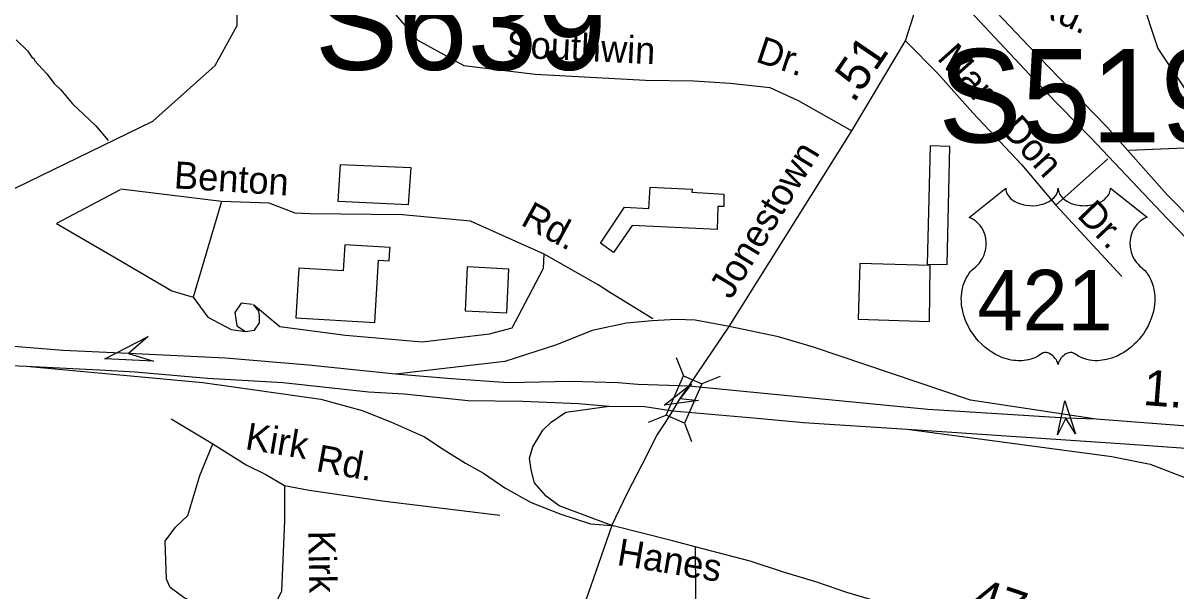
# Model space of a CAD drawing. Extents: x 1547597 to 1699558, y 810033 to 920809.
# Drawn here: x 1602112 to 1606161, y 847300 to 849294 of the extents above; entities that cross this region are included whole.
import ezdxf

# ---------------------------------------------------------------- set-up
doc = ezdxf.new("R2010")
doc.units = 0
for name, color, linetype in [('Exist Cultural Warehouse Building Footprint', 7, 'Continuous'), ('Exist Hydrographic Creek Single Shore', 7, 'Continuous'), ('Exist Hydrographic Misc Water Feature', 7, 'Continuous'), ('Exist Road Non-System Type 51', 7, 'Continuous'), ('Exist Road Non-System Type 51 Label', 7, 'Continuous'), ('Exist Road Primary Interstate Structure Ovrhead Sign Attributed CELL', 7, 'Continuous'), ('Exist Road Primary Interstate Structure Ovrhead Sign Number Label', 7, 'Continuous'), ('Exist Road Primary US Divided Attributed', 7, 'Continuous'), ('Exist Road Primary US Mileage Hundredths English Label', 7, 'Continuous'), ('Exist Road Primary US Ramp 1 Lane  Attributed', 7, 'Continuous'), ('Exist Road Primary US Shield CELL', 7, 'Continuous'), ('Exist Road Primary US Shield Number Label', 7, 'Continuous'), ('Exist Road Secondary Mileage Hundredths English Label', 7, 'Continuous'), ('Exist Road Secondary Structure Standard Bridge Attributed CELL', 7, 'Continuous'), ('Exist Road Secondary Structure Standard Bridge CELL', 7, 'Continuous'), ('Exist Road Secondary Type 51 Attributed', 7, 'Continuous'), ('Exist Road Secondary Type 51 Label', 7, 'Continuous'), ('Exist Utilities Electrical Transmission Line', 7, 'Continuous')]:
    doc.layers.add(name, color=color, linetype=linetype)

msp = doc.modelspace()

# ---------------------------------------------------------------- linework, layer by layer
at = {"layer": 'Exist Cultural Warehouse Building Footprint'}
for points in [[(1605286.8, 848447.3), (1605356.8, 848445.9), (1605366.7, 848861), (1605298, 848862.4)], [(1603227, 848797.3), (1603474, 848786.9), (1603463.9, 848655.4), (1603218.1, 848667.4)], [(1604139.9, 848520.7), (1604223.7, 848647.5), (1604309.6, 848642.4), (1604314.7, 848718.3), (1604461.3, 848710.7), (1604460.9, 848699.7), (1604572.5, 848693), (1604572.5, 848650), (1604552.2, 848650), (1604549.7, 848569), (1604250.5, 848583.1), (1604185.8, 848488.1)], [(1603069.7, 848258.4), (1603347.2, 848242), (1603360.2, 848461.2), (1603398, 848458.9), (1603400.2, 848497.3), (1603400.8, 848506), (1603241.4, 848515.5), (1603236, 848423.8), (1603080.1, 848433)], [(1603671, 848437.5), (1603665, 848283.8), (1603810.6, 848275.9), (1603818.2, 848430.2)], [(1605050.4, 848449.2), (1605044.8, 848254.3), (1605295.6, 848245.9), (1605297, 848442.2)]]:
    msp.add_lwpolyline(points, close=True, dxfattribs=at)
at = {"layer": 'Exist Hydrographic Creek Single Shore'}
msp.add_lwpolyline([(1601996.7, 848672.3), (1602567.6, 848949.6), (1602786.6, 849145.4), (1602863.6, 849285), (1602859.6, 849610.1), (1602806.6, 849988.7), (1602824.7, 850162.3), (1602904.6, 850485.7), (1602936.7, 850702.7), (1602989.1, 850819.4), (1603267.6, 850997.3), (1603446.2, 851092.6), (1603489, 851168.8), (1603543.8, 851395.2), (1603678.6, 851694.4), (1603816.6, 851990.4), (1603873.5, 852138.8)], dxfattribs=at)
at = {"layer": 'Exist Hydrographic Misc Water Feature'}
msp.add_lwpolyline([(1602087.1, 849235.5), (1602128.5, 849194.9), (1602142.3, 849174.7), (1602150.2, 849168.6), (1602152.1, 849162.6), (1602195.5, 849116), (1602220.9, 849081.6), (1602244.6, 849059.3), (1602285.9, 849010.7), (1602366.8, 848933.6), (1602411.2, 848882.2)], dxfattribs=at)
at = {"layer": 'Exist Road Non-System Type 51'}
for points in [[(1603341.7, 849798.4), (1603321, 849576.4), (1603341.5, 849455.7), (1603413.3, 849332.6), (1603495.3, 849235.1), (1603659.4, 849145.2), (1603910.7, 849114.4), (1604297.9, 849093.9), (1604467.1, 849091.3), (1604595.3, 849083.6), (1604733.8, 849068.3), (1604833.8, 849022.1), (1605022.8, 848915.5)], [(1606035.8, 849389.8), (1606097.5, 849204.3), (1606189.1, 849066.9), (1606280.6, 848927.2), (1606321.8, 848883.7)], [(1605210.5, 849232.1), (1605324.1, 849117.5), (1605447.6, 848979.1), (1605617.7, 848797.4), (1605738.3, 848654.7)], [(1606321.8, 848883.7), (1606276, 848858.5), (1605994.6, 848847)], [(1605921.3, 848817.3), (1605738.3, 848654.7)], [(1602452.4, 848708.3), (1602229.3, 848590.2)], [(1602808.8, 848667.2), (1602454.9, 848710.9)], [(1602808.8, 848667.2), (1602708.8, 848331.1)], [(1603942.2, 848482.5), (1603683.2, 848597.9), (1603444.7, 848621), (1603119.1, 848623.6), (1603067.8, 848626.2), (1602975.5, 848662.1), (1602808.8, 848667.2)], [(1605738.3, 848654.7), (1605970.6, 848403.6)], [(1602229.3, 848590.2), (1602444.7, 848464.5), (1602634.4, 848354.2), (1602708.8, 848331.1)], [(1602921.6, 848305.4), (1603013.9, 848228.4), (1603244.7, 848197.6), (1603513.9, 848174.5), (1603749.8, 848202.8), (1603829.3, 848223.3), (1603875.5, 848310.5), (1603939.6, 848433.7), (1603942.2, 848482.5)], [(1604323.6, 848255.1), (1604174.8, 848346.7), (1604131.2, 848374.9), (1603942.2, 848482.5)], [(1602708.8, 848331.1), (1602760.1, 848261.8), (1602842.1, 848218.1), (1602893.4, 848210.5)], [(1602916.5, 848305.4), (1602878, 848310.5), (1602855, 848277.2), (1602862.6, 848231), (1602893.4, 848210.5), (1602924.2, 848215.6), (1602942.1, 848241.2), (1602942.1, 848266.9), (1602939.6, 848282.3), (1602921.6, 848305.4)], [(1602632.2, 847903.9), (1602778.3, 847816.2)], [(1602962.8, 847180.7), (1602833.1, 847202.6), (1602677.9, 847275.7), (1602628.6, 847312.3), (1602615.8, 847341.5), (1602610.3, 847474.9), (1602646.9, 847524.3), (1602690.7, 847564.5), (1602732.7, 847705.2), (1602778.3, 847816.2)], [(1602778.3, 847816.2), (1602895.2, 847743.1), (1602964.6, 847708.3), (1603030.3, 847670.5)], [(1603030.3, 847670.5), (1603030.3, 847546.2), (1603019.4, 847299.5), (1602979.2, 847215.4), (1602962.8, 847180.7)], [(1603030.3, 847670.5), (1603116.1, 847653.5), (1603382.8, 847615.1), (1603786.4, 847565.8)], [(1604179.3, 847529.3), (1604040.1, 847129.7), (1603925.9, 846807)], [(1604471.8, 847454.2), (1604477.1, 846806.5)]]:
    msp.add_lwpolyline(points, dxfattribs=at)
at = {"layer": 'Exist Road Primary Interstate Structure Ovrhead Sign Attributed CELL'}
for points in [[(1602569.3, 848106.7), (1602398.8, 848115.3), (1602550.7, 848193.1), (1602482.2, 848133.2)], [(1605744.9, 847848.5), (1605770.6, 847967.7), (1605808, 847851.6), (1605773.6, 847906.8)]]:
    msp.add_lwpolyline(points, close=True, dxfattribs=at)
at = {"layer": 'Exist Road Primary US Divided Attributed'}
for points in [[(1603419.9, 848061.2), (1603114.3, 848092.3), (1602822.5, 848117.4), (1602482.2, 848133.2), (1602251.6, 848144), (1602064.6, 848159.3), (1601728.5, 848169.4), (1601520.5, 848164.7), (1601065.6, 848149.1), (1600583.5, 848138.5), (1600345.2, 848131.5), (1599996.2, 848126.1), (1599882.8, 848124.5)], [(1599705.6, 848058.6), (1599908.3, 848059.2), (1600130.5, 848064.5), (1600361.8, 848073.3), (1600468.6, 848076), (1600705.6, 848082.6), (1600979.1, 848087.3), (1601274, 848094.3), (1601502.3, 848105), (1601786.7, 848104.7), (1602122.6, 848089.2)], [(1602122.6, 848089.2), (1602379.8, 848076), (1602505.4, 848069.5), (1602759.8, 848047.1), (1603025, 848032), (1603324.9, 847999.1), (1603450.2, 847992.6), (1603675.4, 847968.5), (1603865.5, 847965.8), (1604062, 847958.2), (1604170.7, 847948.4)], [(1604449.6, 848019.4), (1604271.1, 848024.5), (1604201.6, 848030.1), (1604035.6, 848035.1), (1603815.2, 848030.2), (1603616, 848044.4), (1603419.9, 848061.2)], [(1605880.9, 847903.3), (1605773.6, 847906.8), (1605289.3, 847936.9), (1604449.6, 848019.4)], [(1604170.7, 847948.4), (1604294.9, 847947.7), (1604393.5, 847932.6)], [(1604393.5, 847932.6), (1604689.4, 847907.1), (1604852.6, 847891.8), (1605217.1, 847868.3)], [(1605217.1, 847868.3), (1606000.2, 847815.6), (1606342, 847790.1), (1606658.4, 847762.4), (1606838.5, 847750.4), (1607017.4, 847737.7), (1607165.1, 847724), (1607331.3, 847713.2), (1607466.4, 847708.9), (1607585.8, 847712.7), (1607706.7, 847722.7)], [(1606537.3, 847865.3), (1606352.3, 847866.3), (1605880.9, 847903.3)]]:
    msp.add_lwpolyline(points, dxfattribs=at)
at = {"layer": 'Exist Road Primary US Ramp 1 Lane  Attributed'}
for points in [[(1604591.4, 848228.5), (1604472.7, 848251.2), (1604404.9, 848252.6), (1604320.7, 848248.1), (1604230.7, 848239.7), (1604110.3, 848213.9), (1603984.8, 848163.9), (1603804, 848105.3), (1603419.9, 848061.2)], [(1605880.9, 847903.3), (1605439.1, 847969.9), (1604888.2, 848156), (1604764.6, 848191.7), (1604591.4, 848228.5)], [(1602122.6, 848089.2), (1602742.7, 848031.5), (1603158.1, 847973.8), (1603302.4, 847933.4), (1603406.2, 847893), (1603521.6, 847841), (1603590.8, 847794.8), (1603665.8, 847748.7), (1603729.3, 847714), (1603804.3, 847662.1), (1603896.6, 847610.1), (1604000.5, 847569.7), (1604104.3, 847535.1), (1604179.3, 847529.3)], [(1604179.3, 847529.3), (1603994.7, 847598.6), (1603948.6, 847633.2), (1603908.2, 847679.4), (1603896.6, 847725.6), (1603890.9, 847766), (1603902.4, 847806.4), (1603919.7, 847835.3), (1603937, 847864.1), (1603965.9, 847893), (1604017.8, 847927.6), (1604170.7, 847948.4)], [(1605217.1, 847868.3), (1605935.1, 847772.4), (1606069.9, 847744.7), (1606258.6, 847672.4), (1606386.7, 847609.8), (1606623.3, 847465.6), (1606799.3, 847336.5), (1606924.5, 847240.2)]]:
    msp.add_lwpolyline(points, dxfattribs=at)
at = {"layer": 'Exist Road Primary US Shield CELL'}
msp.add_lwpolyline([(1605562.7, 848714.2), (1605563.1, 848708.8), (1605564.4, 848702.5), (1605565.3, 848699.3), (1605568.3, 848693), (1605573.2, 848685.7), (1605580, 848678.4), (1605587.6, 848672.1), (1605592.8, 848668.8), (1605601.6, 848664.1), (1605611.5, 848659.9), (1605622.6, 848656.7), (1605633.9, 848654.4), (1605646.3, 848653.1), (1605658.5, 848652.8), (1605671.8, 848653.8), (1605686.3, 848656.6), (1605693.1, 848658.4), (1605700.6, 848661), (1605707.6, 848663.9), (1605715.3, 848668), (1605721.4, 848671.9), (1605726.2, 848675.4), (1605733.1, 848681.9), (1605738.5, 848688.7), (1605740.8, 848692.5), (1605742.8, 848696.1), (1605745.5, 848703.9), (1605746.2, 848707.3), (1605746.8, 848714.4), (1605747.2, 848708.5), (1605747.8, 848704.7), (1605748.8, 848701.1), (1605750.3, 848697.2), (1605753.1, 848691.7), (1605756.1, 848687.2), (1605761.8, 848680.4), (1605765.4, 848677.1), (1605768.7, 848674.4), (1605777.4, 848668.4), (1605787.6, 848663.2), (1605792.6, 848661), (1605797.8, 848659.2), (1605804.3, 848657.2), (1605811.1, 848655.6), (1605817.8, 848654.5), (1605824.6, 848653.5), (1605831.6, 848653), (1605837.3, 848652.8), (1605844.3, 848652.9), (1605850.7, 848653.3), (1605857.3, 848654.1), (1605864.6, 848655.3), (1605870.5, 848656.6), (1605878.2, 848658.6), (1605885.2, 848661.1), (1605891.4, 848663.8), (1605899.3, 848668), (1605905.8, 848672), (1605910.5, 848675.8), (1605916.1, 848681), (1605921.4, 848687.1), (1605924.5, 848691.6), (1605926.8, 848696.2), (1605928.8, 848701.1), (1605930.1, 848706.3), (1605930.7, 848710.7), (1605930.8, 848714.6), (1606059.4, 848612.1), (1606056.4, 848611), (1606049.4, 848607.5), (1606043.8, 848604.3), (1606035, 848598), (1606031.2, 848594.6), (1606027.4, 848591.1), (1606023.9, 848587.3), (1606020.8, 848583.7), (1606017.1, 848578.5), (1606013.7, 848573.4), (1606010.5, 848567.7), (1606008.1, 848562.7), (1606004.1, 848552.4), (1606002.2, 848545.8), (1606001, 848540.3), (1605999.5, 848528.8), (1605999.1, 848523.4), (1605999.1, 848518), (1605999.4, 848512.3), (1606000, 848506.8), (1606000.9, 848501.1), (1606001.9, 848496.1), (1606003.5, 848489.9), (1606005.7, 848482.8), (1606008.5, 848475.9), (1606014.4, 848464.7), (1606022, 848453.3), (1606027.4, 848446.9), (1606032.7, 848441.4), (1606040.6, 848434.8), (1606044.9, 848431), (1606049.9, 848426), (1606057.9, 848416.7), (1606061.2, 848412.3), (1606064.5, 848407.3), (1606067.5, 848402.2), (1606070.6, 848396.8), (1606073, 848392), (1606077.5, 848381), (1606080.8, 848370.2), (1606082.3, 848364.6), (1606084.7, 848352), (1606085.6, 848345.8), (1606086.6, 848333.5), (1606086.7, 848318.6), (1606085.5, 848304.4), (1606082.9, 848287.9), (1606080.7, 848278.1), (1606077.3, 848266.6), (1606074, 848256.6), (1606068.1, 848242), (1606062.9, 848231.3), (1606056.2, 848218.9), (1606051.5, 848211.4), (1606046.1, 848203.3), (1606039.4, 848194), (1606031.5, 848184.1), (1606022, 848173.7), (1606014.3, 848166.1), (1606004.3, 848157.1), (1605998.2, 848152.1), (1605989.6, 848145.5), (1605977.7, 848137.6), (1605966, 848130.9), (1605956.1, 848125.8), (1605947.3, 848122), (1605935.9, 848117.7), (1605916.9, 848112.4), (1605910, 848111), (1605901.8, 848109.8), (1605894.1, 848109), (1605886.7, 848108.5), (1605876.6, 848108.5), (1605866.7, 848109.3), (1605857.3, 848110.7), (1605847.5, 848112.7), (1605837.2, 848115.8), (1605827.9, 848119.4), (1605818.5, 848124), (1605802.6, 848134.1), (1605798, 848136.5), (1605795.4, 848137.2), (1605789.2, 848137.5), (1605783.5, 848136.3), (1605777.6, 848133.9), (1605774, 848132), (1605769.2, 848128.9), (1605765.6, 848126), (1605761.2, 848121.8), (1605758.1, 848118.3), (1605755.8, 848115.6), (1605751.3, 848108.5), (1605749.8, 848105.2), (1605748.1, 848100.9), (1605746.6, 848094.5), (1605744.6, 848102.5), (1605742.2, 848107.9), (1605739.5, 848112.4), (1605736.7, 848116.4), (1605732.2, 848121.6), (1605728.1, 848125.5), (1605723.3, 848129.4), (1605718.1, 848132.5), (1605714, 848134.7), (1605710.2, 848136.1), (1605705.6, 848137.3), (1605701.8, 848137.6), (1605698.6, 848137.5), (1605694.4, 848136.5), (1605688.5, 848132.3), (1605683, 848128.5), (1605677, 848124.8), (1605669.9, 848121), (1605664.7, 848118.6), (1605658.4, 848116.1), (1605651.1, 848113.7), (1605643.2, 848111.7), (1605635.1, 848110.1), (1605628, 848108.9), (1605620.3, 848108.2), (1605613.4, 848108), (1605606.2, 848108.1), (1605599.4, 848108.6), (1605591.6, 848109.3), (1605581.9, 848110.7), (1605573.8, 848112.6), (1605565.3, 848114.8), (1605556.6, 848117.6), (1605547.2, 848121.2), (1605535.5, 848126.2), (1605527.4, 848130.4), (1605514.6, 848137.8), (1605499.5, 848148.2), (1605488.2, 848157.4), (1605479.9, 848164.9), (1605467.6, 848177.4), (1605460.5, 848185.5), (1605449.2, 848200.1), (1605442, 848210.7), (1605437.3, 848218.4), (1605430.5, 848230.9), (1605426.7, 848238.7), (1605421.9, 848250.1), (1605418, 848260.5), (1605414.8, 848270.4), (1605413.1, 848276.7), (1605410.7, 848287.7), (1605409.2, 848295.5), (1605407.8, 848306.3), (1605407, 848317.6), (1605406.8, 848328), (1605407.1, 848336.7), (1605408.1, 848346.8), (1605409.8, 848357.5), (1605411.8, 848366.7), (1605413.7, 848373.3), (1605416.4, 848381.3), (1605420, 848390.2), (1605424.3, 848398.7), (1605428.3, 848405.8), (1605433.4, 848413.4), (1605438.5, 848419.9), (1605445, 848427), (1605451.9, 848433.5), (1605458.1, 848438.6), (1605465.6, 848445.9), (1605469.4, 848450.3), (1605474.1, 848456.5), (1605477.8, 848462.2), (1605480.8, 848467.3), (1605484.7, 848474.8), (1605487.1, 848480.4), (1605490, 848489.1), (1605491.5, 848495.2), (1605493, 848503), (1605494, 848510.4), (1605494.4, 848519.6), (1605494.2, 848527.1), (1605493.2, 848536), (1605491.5, 848544.6), (1605489.5, 848552), (1605486.3, 848560.5), (1605483.4, 848566.7), (1605478.4, 848575.2), (1605473, 848583), (1605467.3, 848589.4), (1605461.6, 848595.1), (1605456.1, 848599.3), (1605450.9, 848603.1), (1605444.4, 848607), (1605438.1, 848610.1), (1605434.1, 848611.7)], close=True, dxfattribs=at)
at = {"layer": 'Exist Road Secondary Structure Standard Bridge Attributed CELL'}
msp.add_lwpolyline([(1604484, 847968.8), (1604363.2, 847952.5), (1604459.6, 848027), (1604419.4, 847976)], close=True, dxfattribs=at)
at = {"layer": 'Exist Road Secondary Structure Standard Bridge CELL'}
for p, q in [((1604405.5, 848120), (1604430.7, 848055.7)), ((1604559.6, 848052.6), (1604495.3, 848027.5)), ((1604371.3, 847916.8), (1604307.1, 847891.6)), ((1604434.5, 847889.1), (1604459.7, 847824.9))]:
    msp.add_line(p, q, dxfattribs=at)
msp.add_lwpolyline([(1604495.3, 848027.5), (1604434.8, 847889), (1604370.1, 847917.3), (1604430.7, 848055.7)], close=True, dxfattribs=at)
at = {"layer": 'Exist Road Secondary Type 51 Attributed'}
for points in [[(1604591.4, 848228.5), (1605022.8, 848915.5), (1605210.5, 849232.1), (1605238.8, 849319.1), (1605246.1, 849359.5), (1605344.6, 849615.8), (1605413.1, 849898), (1605429.8, 850136.9), (1605482.6, 850567.3)], [(1604449.6, 848019.4), (1604591.4, 848228.5)], [(1604393.5, 847932.6), (1604419.4, 847976), (1604449.6, 848019.4)], [(1604179.3, 847529.3), (1604235, 847644.8), (1604286.4, 847743.8), (1604337.4, 847845.9), (1604368, 847891.8), (1604393.5, 847932.6)], [(1606440, 846611.4), (1606359.3, 846676), (1606274.3, 846750.5), (1606118.8, 846874.7), (1605986.8, 846962.7), (1605857.4, 847007.2), (1605697.6, 847074.1), (1605526.1, 847132.2), (1605374.1, 847183.4), (1605199.3, 847236.8), (1605004.7, 847294.4), (1604899.2, 847330.9), (1604782.3, 847365.6), (1604664.8, 847404), (1604471.8, 847454.2), (1604392.8, 847476), (1604179.3, 847529.3)]]:
    msp.add_lwpolyline(points, dxfattribs=at)
at = {"layer": 'Exist Utilities Electrical Transmission Line'}
for points in [[(1604894, 852252.3), (1604822.4, 851651.8), (1604771.8, 851249.6), (1604747, 851053.4), (1604709.3, 850694.2), (1604672.5, 850388.9), (1604649.9, 850219.5), (1604652.9, 850163.4), (1604749.3, 850060), (1604859.2, 849942.3), (1605014.6, 849789.9), (1605230.5, 849554.8), (1605452.6, 849319.3), (1605700, 849055.6), (1605861.2, 848891), (1606130.4, 848607), (1606269.9, 848462.9)], [(1604930.9, 852059.8), (1604878.1, 851633.1), (1604825.9, 851244.1), (1604793.8, 850982.8), (1604746.2, 850617.8), (1604713, 850292.5), (1604707.8, 850216.5), (1604748.7, 850157.9), (1604876.3, 850028.8), (1605000.3, 849896), (1605285.3, 849603.7), (1605485.5, 849380.7), (1605711.4, 849141.4), (1605917.8, 848930.1), (1606129.9, 848690.8), (1606414.8, 848402.5)]]:
    msp.add_lwpolyline(points, dxfattribs=at)

# ---------------------------------------------------------------- texts
at = {"layer": 'Exist Road Non-System Type 51 Label'}
for s, rotation, p in [('Rd.', 335.4212, (1605656, 849334.9)), ('Southwin', 357.2807, (1603807.9, 849174.1)), ('Dr.', 341.5579, (1604680.7, 849159.5)), ('Mar', 311.7385, (1605318.7, 849168.8)), ('Don', 312.4256, (1605543.7, 848916.1)), ('Benton', 356.2648, (1602639.9, 848714.1)), ('Rd.', 331.483, (1603855.5, 848587.4)), ('Dr.', 313.9798, (1605809.6, 848615.6)), ('Kirk', 350.5893, (1602888.6, 847798.1)), ('Rd.', 349.643, (1603137.3, 847721.1)), ('Kirk', 270.9893, (1603113.6, 847510.8))]:
    msp.add_text(s, height=95, rotation=rotation, dxfattribs=at).set_placement(p)
at = {"layer": 'Exist Road Primary Interstate Structure Ovrhead Sign Number Label'}
for s, p in [('S639', (1603136.5, 849129.9)), ('S519', (1605326.1, 848874.8))]:
    msp.add_text(s, height=328.08, dxfattribs=at).set_placement(p)
at = {"layer": 'Exist Road Primary US Mileage Hundredths English Label'}
msp.add_text('1.01', height=125, rotation=355.5128, dxfattribs=at).set_placement((1606042.8, 847953.3))
at = {"layer": 'Exist Road Primary US Shield Number Label'}
msp.add_text('421', height=212.5, dxfattribs=at).set_placement((1605463.9, 848214.9))
at = {"layer": 'Exist Road Secondary Mileage Hundredths English Label'}
for s, height, rotation, p in [('.51', 120, 55.6768, (1605028.8, 849010.2)), ('.47', 125, 341.4043, (1605389.2, 847244.2))]:
    msp.add_text(s, height=height, rotation=rotation, dxfattribs=at).set_placement(p)
at = {"layer": 'Exist Road Secondary Type 51 Label'}
for s, rotation, p in [('Jonestown', 58.8065, (1604598, 848320.3)), ('Hanes', 350.5577, (1604194.3, 847391.6))]:
    msp.add_text(s, height=95, rotation=rotation, dxfattribs=at).set_placement(p)

doc.saveas('drawing.dxf')
